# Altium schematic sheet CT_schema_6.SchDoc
size 479 x 328 mm
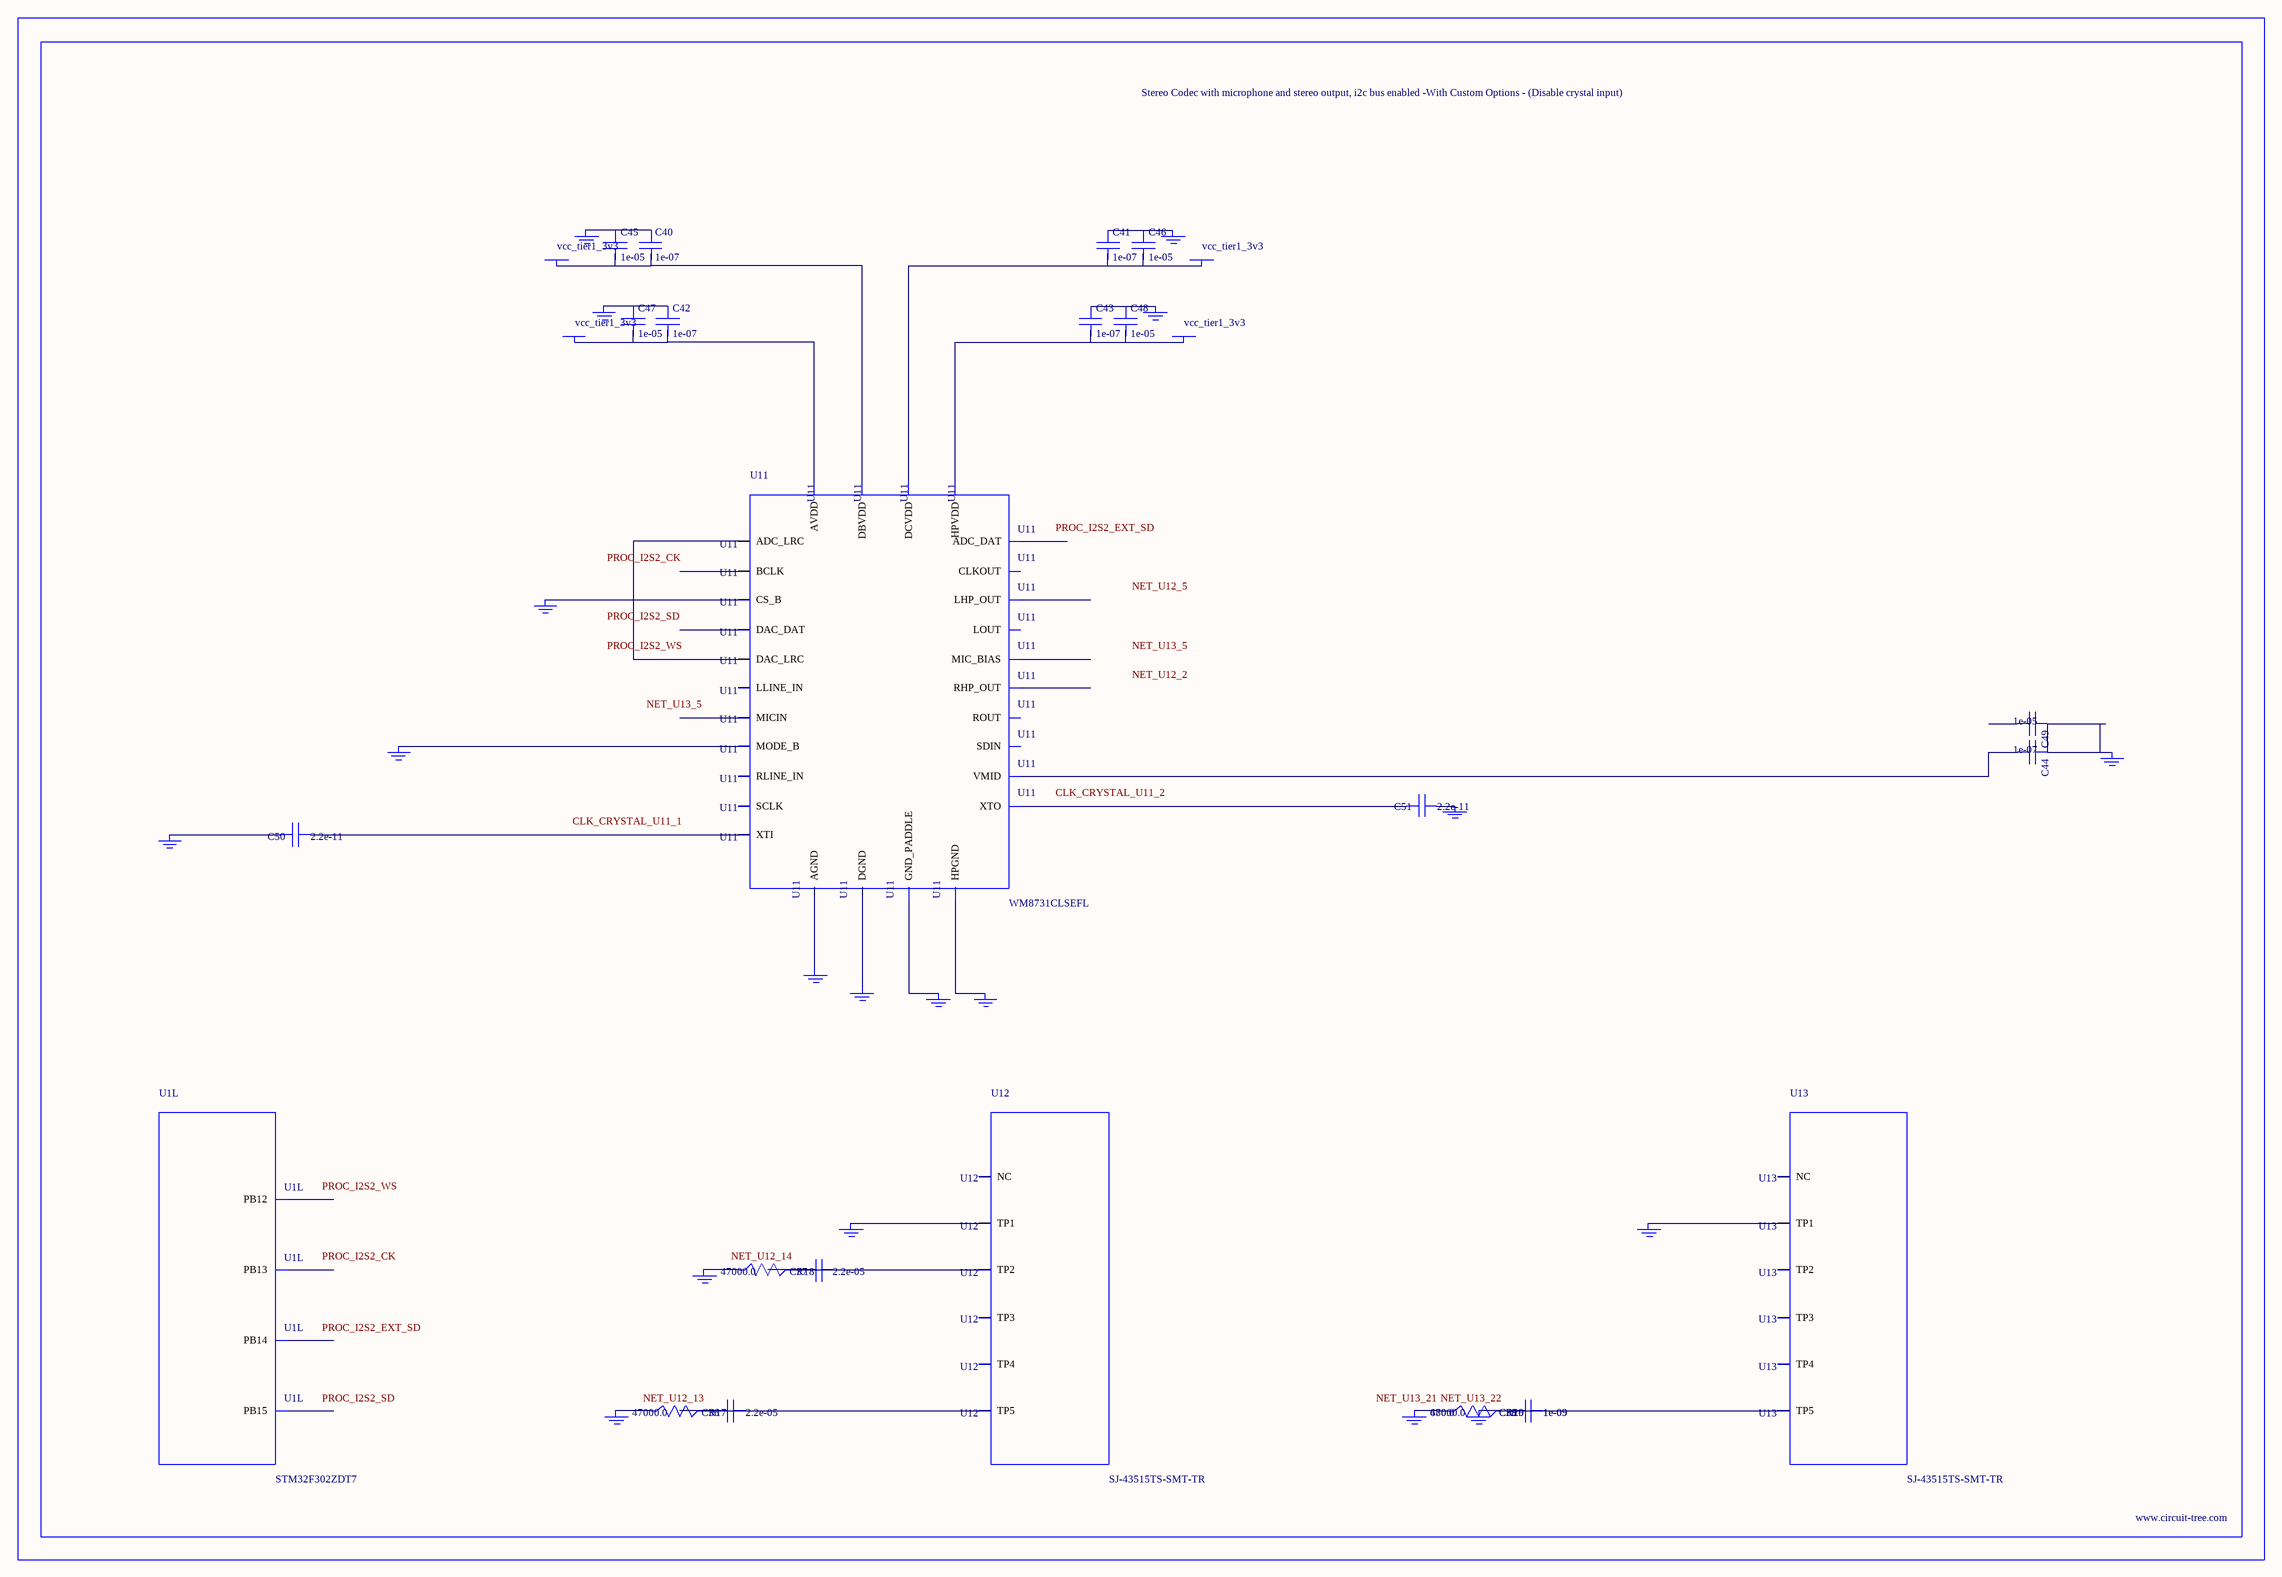
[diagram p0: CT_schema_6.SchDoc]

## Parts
BORDER5  (no value)
C36  2.2e-05  [C1210]
C37  2.2e-05  [C1210]
C38  1e-09  [C0402]
C39  1e-09  [C0402]
C40  1e-07  [C0402]
C41  1e-07  [C0402]
C42  1e-07  [C0402]
C43  1e-07  [C0402]
C44  1e-07  [C0402]
C45  1e-05  [C0805]
C46  1e-05  [C0805]
C47  1e-05  [C0805]
C48  1e-05  [C0805]
C49  1e-05  [C0805]
C50  2.2e-11  [C0402]
C51  2.2e-11  [C0402]
GND_INSTANCE_5_0  (no value)
GND_INSTANCE_5_1  (no value)
GND_INSTANCE_5_2  (no value)
GND_INSTANCE_5_3  (no value)
GND_INSTANCE_5_4  (no value)
GND_INSTANCE_5_5  (no value)
GND_INSTANCE_5_6  (no value)
GND_INSTANCE_5_7  (no value)
GND_INSTANCE_5_8  (no value)
GND_INSTANCE_5_9  (no value)
GND_INSTANCE_5_10  (no value)
GND_INSTANCE_5_11  (no value)
GND_INSTANCE_5_12  (no value)
GND_INSTANCE_5_13  (no value)
GND_INSTANCE_5_14  (no value)
GND_INSTANCE_5_15  (no value)
GND_INSTANCE_5_16  (no value)
GND_INSTANCE_5_17  (no value)
GND_INSTANCE_5_18  (no value)
POWER_INSTANCE_5_0  vcc_tier1_3v3
POWER_INSTANCE_5_1  vcc_tier1_3v3
POWER_INSTANCE_5_2  vcc_tier1_3v3
POWER_INSTANCE_5_3  vcc_tier1_3v3
R17  47000.0  [R0603]
R18  47000.0  [R0603]
R19  47000.0  [R0603]
R20  680.0  [R0603]
U1  STM32F302ZDT7  [LQFP144]  (part L of 12)
U11  WM8731CLSEFL  [QFN-28]
U12  SJ-43515TS-SMT-TR  [SJ-43515TS-SMT-TR]
U13  SJ-43515TS-SMT-TR  [SJ-43515TS-SMT-TR]

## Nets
NetC36_1: C36.1 C36.2 R17.2 U12.5(TP5)
NetC37_1: C37.1 C37.2 R18.2 U12.2(TP2)
NetC38_1: C38.1 C38.2 C39.1 C39.2 GND_INSTANCE_5_18.0(GND) R19.2 R20.2 U13.5(TP5)
NetC40_1: C40.1 C45.1 GND_INSTANCE_5_3.0(GND)
NetC40_2: C40.2 C45.2 POWER_INSTANCE_5_1.0(PWR) U11.5(DBVDD)
NetC41_1: C41.1 C46.1 GND_INSTANCE_5_2.0(GND)
NetC41_2: C41.2 C46.2 POWER_INSTANCE_5_0.0(PWR) U11.3(DCVDD)
NetC42_1: C42.1 C47.1 GND_INSTANCE_5_6.0(GND)
NetC42_2: C42.2 C47.2 POWER_INSTANCE_5_3.0(PWR) U11.18(AVDD)
NetC43_1: C43.1 C48.1 GND_INSTANCE_5_4.0(GND)
NetC43_2: C43.2 C48.2 POWER_INSTANCE_5_2.0(PWR) U11.12(HPVDD)
NetC44_1: C44.1 C49.1 GND_INSTANCE_5_7.0(GND)
NetC44_2: C44.2 U11.20(VMID)
NetC50_1: C50.1 U11.1(XTI)
NetC50_2: C50.2 GND_INSTANCE_5_0.0(GND)
NetC51_1: C51.1 GND_INSTANCE_5_1.0(GND)
NetC51_2: C51.2 U11.2(XTO)
NetGND_INSTANCE_5_5_0: GND_INSTANCE_5_5.0(GND) U11.15(HPGND)
NetGND_INSTANCE_5_8_0: GND_INSTANCE_5_8.0(GND) U11.25(MODE_B)
NetGND_INSTANCE_5_9_0: GND_INSTANCE_5_9.0(GND) U11.26(CS_B)
NetGND_INSTANCE_5_10_0: GND_INSTANCE_5_10.0(GND) U11.29(GND_PADDLE)
NetGND_INSTANCE_5_11_0: GND_INSTANCE_5_11.0(GND) U11.4(DGND)
NetGND_INSTANCE_5_12_0: GND_INSTANCE_5_12.0(GND) U11.19(AGND)
NetGND_INSTANCE_5_13_0: GND_INSTANCE_5_13.0(GND) U12.1(TP1)
NetGND_INSTANCE_5_14_0: GND_INSTANCE_5_14.0(GND) R18.1
NetGND_INSTANCE_5_15_0: GND_INSTANCE_5_15.0(GND) R17.1
NetGND_INSTANCE_5_16_0: GND_INSTANCE_5_16.0(GND) U13.1(TP1)
NetGND_INSTANCE_5_17_0: GND_INSTANCE_5_17.0(GND) R19.1 R20.1
NetU11_9: U11.9(DAC_LRC) U11.11(ADC_LRC)

Not connected (* = marked no-connect by the designer): C49 2; U1 73(PB12) 74(PB13) 75(PB14) 76(PB15); U11 6(CLKOUT) 7(BCLK) 8(DAC_DAT) 10(ADC_DAT) 13(LHP_OUT) 14(RHP_OUT) 16(LOUT) 17(ROUT) 21(MIC_BIAS) 22(MICIN) 23(RLINE_IN) 24(LLINE_IN) 27(SDIN) 28(SCLK); U12 3(TP3) 4(TP4) 6(NC); U13 2(TP2) 3(TP3) 4(TP4) 6(NC)

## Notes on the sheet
- Labels drawn without touching a wire or pin: CLK_CRYSTAL_U11_1, CLK_CRYSTAL_U11_2, NET_U12_2, NET_U12_5, NET_U12_13, NET_U12_14, NET_U13_5, NET_U13_21, NET_U13_22, PROC_I2S2_CK, PROC_I2S2_EXT_SD, PROC_I2S2_SD, PROC_I2S2_WS

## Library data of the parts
BORDER5 = BORDER_PAGE5
C36 C37 = C1210C224K5RACTU
C38 C39 = C0402C102K3RAC
C40-C44 = C0402C104K3RACTU
C45-C49 = C0805C106K8RACTU
C50 C51 = C0402C220K3RAC
GND_INSTANCE_5_0-GND_INSTANCE_5_18 = GND
POWER_INSTANCE_5_0-POWER_INSTANCE_5_3 = PWR
R17-R19 = RC0603JR-0747KL
R20 = RC0603JR-07680RL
